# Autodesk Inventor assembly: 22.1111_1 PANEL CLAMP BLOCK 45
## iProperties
Created: 2008-12
Part Number: 22.1111_1 PANEL CLAMP BLOCK 45
Document SubType Name: Assembly
Designer: Administrator
Author: Administrator
